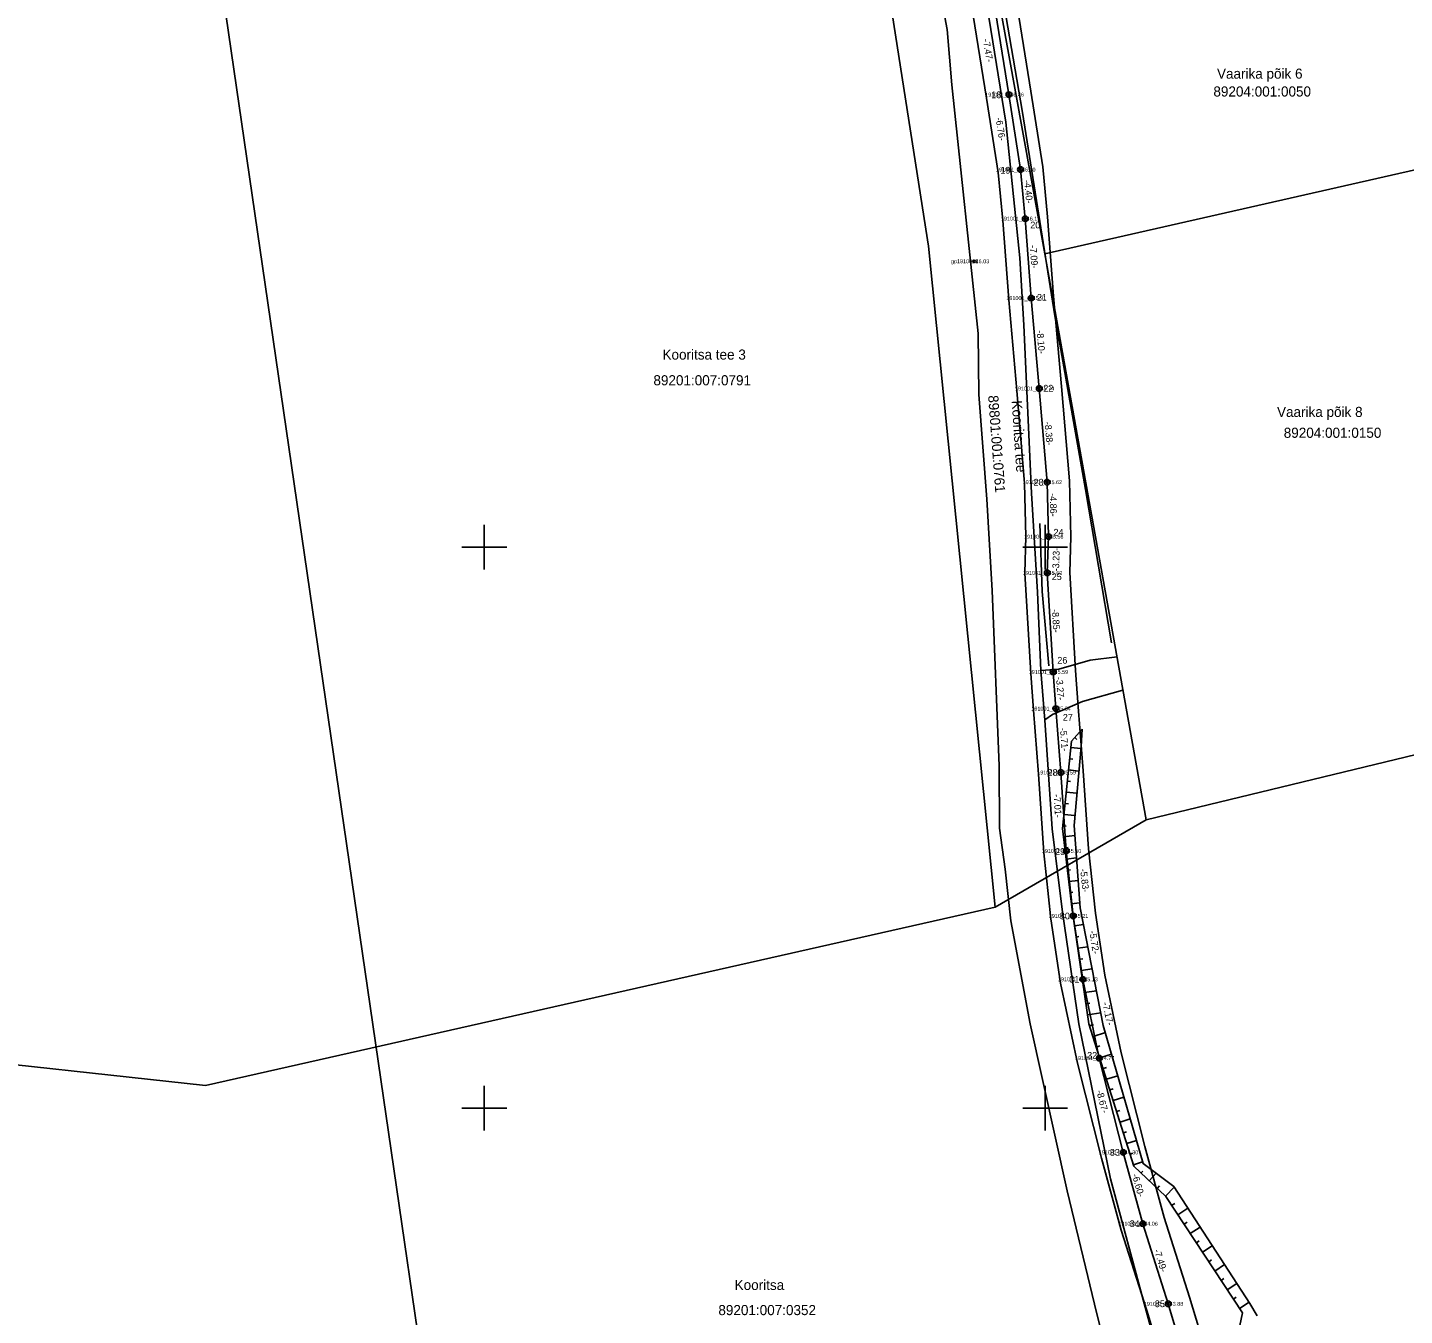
# Model space of a CAD drawing. Extents: x 604066 to 604956, y 6473634 to 6474346.
# Drawn here: x 604559.3 to 604682, y 6473831.5 to 6473946.3 of the extents above; entities that cross this region are included whole.
import ezdxf

# ---------------------------------------------------------------- set-up
doc = ezdxf.new("R2010")
doc.units = 0
for name, color, linetype in [('AED', 7, 'Continuous'), ('JOONSIDE', 7, 'Continuous'), ('KOORDPUNKT', 7, 'Continuous'), ('MOOTKORG', 7, 'Continuous'), ('MOOTMPUNKT', 7, 'Continuous'), ('MOOTNR', 7, 'Continuous'), ('MOOTPIIR', 7, 'Continuous'), ('PIIR', 7, 'Continuous'), ('RELJEEF', 7, 'Continuous'), ('SITRASS', 7, 'Continuous'), ('TEE', 7, 'Continuous'), ('VEEKOGU', 7, 'Continuous'), ('VORK', 7, 'Continuous'), ('VORMISTUS', 7, 'Continuous')]:
    doc.layers.add(name, color=color, linetype=linetype)

msp = doc.modelspace()

# ---------------------------------------------------------------- linework, layer by layer
at = {"layer": 'AED'}
for points in [[(604649.16, 6474001.13), (604643.74, 6473999.92), (604641.11, 6473999.16), (604639.47, 6473996.69), (604638.82, 6473994.42), (604638.66, 6473991.42), (604639.13, 6473988.4), (604641.21, 6473976.45), (604642.8, 6473969.17), (604644.69, 6473957.97), (604647.99, 6473938.75), (604650.86, 6473920.61), (604653.59, 6473905.15), (604655.9, 6473891.46)], [(604649.52, 6473902.1), (604649.73, 6473896.04), (604650.32, 6473889.41)]]:
    msp.add_lwpolyline(points, dxfattribs=at)
at = {"layer": 'KOORDPUNKT'}
for centre, radius in [((604646.76, 6473940.34), 0.25), ((604646.76, 6473940.34), 0.0221), ((604646.76, 6473940.34), 0.025), ((604646.76, 6473940.34), 0.0161), ((604646.76, 6473940.34), 0.0191), ((604646.76, 6473940.34), 0.0102), ((604646.76, 6473940.34), 0.0132), ((604646.76, 6473940.34), 0.00726), ((604646.76, 6473940.34), 0.0043), ((604647.79, 6473933.66), 0.25), ((604647.79, 6473933.66), 0.0191), ((604647.79, 6473933.66), 0.0221), ((604647.79, 6473933.66), 0.025), ((604647.79, 6473933.66), 0.0161), ((604647.79, 6473933.66), 0.0102), ((604647.79, 6473933.66), 0.0132), ((604647.79, 6473933.66), 0.00726), ((604647.79, 6473933.66), 0.0043), ((604648.22, 6473929.28), 0.25), ((604648.22, 6473929.28), 0.025), ((604648.22, 6473929.28), 0.0161), ((604648.22, 6473929.28), 0.0191), ((604648.22, 6473929.28), 0.0221), ((604648.22, 6473929.28), 0.0043), ((604648.22, 6473929.28), 0.00726), ((604648.22, 6473929.28), 0.0102), ((604648.22, 6473929.28), 0.0132), ((604648.74, 6473922.21), 0.25), ((604648.74, 6473922.21), 0.025), ((604648.74, 6473922.21), 0.0161), ((604648.74, 6473922.21), 0.0191), ((604648.74, 6473922.21), 0.0221), ((604648.74, 6473922.21), 0.00726), ((604648.74, 6473922.21), 0.0102), ((604648.74, 6473922.21), 0.0132), ((604648.74, 6473922.21), 0.0043), ((604649.46, 6473914.15), 0.25), ((604649.46, 6473914.15), 0.0221), ((604649.46, 6473914.15), 0.025), ((604649.46, 6473914.15), 0.0102), ((604649.46, 6473914.15), 0.0132), ((604649.46, 6473914.15), 0.0161), ((604649.46, 6473914.15), 0.0191), ((604649.46, 6473914.15), 0.0043), ((604649.46, 6473914.15), 0.00726), ((604650.16, 6473905.79), 0.25), ((604650.16, 6473905.79), 0.0221), ((604650.16, 6473905.79), 0.025), ((604650.16, 6473905.79), 0.0132), ((604650.16, 6473905.79), 0.0161), ((604650.16, 6473905.79), 0.0191), ((604650.16, 6473905.79), 0.0043), ((604650.16, 6473905.79), 0.00726), ((604650.16, 6473905.79), 0.0102), ((604650.28, 6473900.94), 0.25), ((604650.28, 6473900.94), 0.025), ((604650.28, 6473900.94), 0.0191), ((604650.28, 6473900.94), 0.0221), ((604650.28, 6473900.94), 0.0161), ((604650.28, 6473900.94), 0.0102), ((604650.28, 6473900.94), 0.0132), ((604650.28, 6473900.94), 0.00726), ((604650.28, 6473900.94), 0.0043), ((604650.18, 6473897.71), 0.25), ((604650.18, 6473897.71), 0.0221), ((604650.18, 6473897.71), 0.025), ((604650.18, 6473897.71), 0.0191), ((604650.18, 6473897.71), 0.0102), ((604650.18, 6473897.71), 0.0132), ((604650.18, 6473897.71), 0.0161), ((604650.18, 6473897.71), 0.0043), ((604650.18, 6473897.71), 0.00726), ((604650.7, 6473888.87), 0.25), ((604650.7, 6473888.87), 0.0221), ((604650.7, 6473888.87), 0.025), ((604650.7, 6473888.87), 0.0161), ((604650.7, 6473888.87), 0.0191), ((604650.7, 6473888.87), 0.0132), ((604650.7, 6473888.87), 0.00726), ((604650.7, 6473888.87), 0.0102), ((604650.7, 6473888.87), 0.0043), ((604650.94, 6473885.61), 0.25), ((604650.94, 6473885.61), 0.025), ((604650.94, 6473885.61), 0.0191), ((604650.94, 6473885.61), 0.0221), ((604650.94, 6473885.61), 0.0161), ((604650.94, 6473885.61), 0.0102), ((604650.94, 6473885.61), 0.0132), ((604650.94, 6473885.61), 0.00726), ((604650.94, 6473885.61), 0.0043), ((604651.39, 6473879.92), 0.25), ((604651.39, 6473879.92), 0.0191), ((604651.39, 6473879.92), 0.0221), ((604651.39, 6473879.92), 0.025), ((604651.39, 6473879.92), 0.0102), ((604651.39, 6473879.92), 0.0132), ((604651.39, 6473879.92), 0.0161), ((604651.39, 6473879.92), 0.00726), ((604651.39, 6473879.92), 0.0043), ((604651.87, 6473872.93), 0.25), ((604651.87, 6473872.93), 0.0191), ((604651.87, 6473872.93), 0.0221), ((604651.87, 6473872.93), 0.025), ((604651.87, 6473872.93), 0.0102), ((604651.87, 6473872.93), 0.0132), ((604651.87, 6473872.93), 0.0161), ((604651.87, 6473872.93), 0.0043), ((604651.87, 6473872.93), 0.00726), ((604652.49, 6473867.13), 0.25), ((604652.49, 6473867.13), 0.0221), ((604652.49, 6473867.13), 0.025), ((604652.49, 6473867.13), 0.0132), ((604652.49, 6473867.13), 0.0161), ((604652.49, 6473867.13), 0.0191), ((604652.49, 6473867.13), 0.0043), ((604652.49, 6473867.13), 0.00726), ((604652.49, 6473867.13), 0.0102), ((604653.34, 6473861.48), 0.25), ((604653.34, 6473861.48), 0.025), ((604653.34, 6473861.48), 0.0132), ((604653.34, 6473861.48), 0.0161), ((604653.34, 6473861.48), 0.0191), ((604653.34, 6473861.48), 0.0221), ((604653.34, 6473861.48), 0.0043), ((604653.34, 6473861.48), 0.00726), ((604653.34, 6473861.48), 0.0102), ((604654.82, 6473854.46), 0.25), ((604654.82, 6473854.46), 0.0221), ((604654.82, 6473854.46), 0.025), ((604654.82, 6473854.46), 0.0161), ((604654.82, 6473854.46), 0.0191), ((604654.82, 6473854.46), 0.0102), ((604654.82, 6473854.46), 0.0132), ((604654.82, 6473854.46), 0.00726), ((604654.82, 6473854.46), 0.0043), ((604656.95, 6473846.06), 0.25), ((604656.95, 6473846.06), 0.025), ((604656.95, 6473846.06), 0.0161), ((604656.95, 6473846.06), 0.0191), ((604656.95, 6473846.06), 0.0221), ((604656.95, 6473846.06), 0.0132), ((604656.95, 6473846.06), 0.00726), ((604656.95, 6473846.06), 0.0102), ((604656.95, 6473846.06), 0.0043), ((604658.69, 6473839.7), 0.25), ((604658.69, 6473839.7), 0.0191), ((604658.69, 6473839.7), 0.0221), ((604658.69, 6473839.7), 0.025), ((604658.69, 6473839.7), 0.0102), ((604658.69, 6473839.7), 0.0132), ((604658.69, 6473839.7), 0.0161), ((604658.69, 6473839.7), 0.0043), ((604658.69, 6473839.7), 0.00726), ((604660.96, 6473832.56), 0.25), ((604660.96, 6473832.56), 0.025), ((604660.96, 6473832.56), 0.0161), ((604660.96, 6473832.56), 0.0191), ((604660.96, 6473832.56), 0.0221), ((604660.96, 6473832.56), 0.00726), ((604660.96, 6473832.56), 0.0102), ((604660.96, 6473832.56), 0.0132), ((604660.96, 6473832.56), 0.0043)]:
    msp.add_circle(centre, radius, dxfattribs=at)
at = {"layer": 'MOOTMPUNKT'}
for centre in [(604646.76, 6473940.34), (604647.79, 6473933.66), (604648.22, 6473929.28), (604643.66, 6473925.49), (604648.74, 6473922.21), (604649.46, 6473914.15), (604650.16, 6473905.79), (604650.28, 6473900.94), (604650.18, 6473897.71), (604650.7, 6473888.87), (604650.94, 6473885.61), (604651.39, 6473879.92), (604651.87, 6473872.93), (604652.49, 6473867.13), (604653.34, 6473861.48), (604654.82, 6473854.46), (604656.95, 6473846.06), (604658.69, 6473839.7), (604660.96, 6473832.56)]:
    msp.add_circle(centre, 0.1, dxfattribs=at)
at = {"layer": 'MOOTPIIR'}
for points in [[(604665.14, 6473825.6), (604662.87, 6473833.15), (604660.61, 6473840.26), (604658.88, 6473846.57), (604656.77, 6473854.92), (604655.31, 6473861.84), (604654.47, 6473867.39), (604653.87, 6473873.1), (604653.39, 6473880.07), (604652.94, 6473885.76), (604652.7, 6473889.01), (604652.18, 6473897.73), (604652.28, 6473900.93), (604652.15, 6473905.9), (604651.46, 6473914.32), (604650.73, 6473922.37), (604650.21, 6473929.45), (604649.78, 6473933.91), (604648.73, 6473940.65), (604647.53, 6473948.05)], [(604643.58, 6473947.38), (604644.78, 6473940.03), (604645.81, 6473933.41), (604646.23, 6473929.11), (604646.75, 6473922.05), (604647.47, 6473913.97), (604648.16, 6473905.69), (604648.28, 6473900.94), (604648.18, 6473897.68), (604648.71, 6473888.74), (604648.95, 6473885.46), (604649.4, 6473879.77), (604649.88, 6473872.75), (604650.5, 6473866.88), (604651.37, 6473861.13), (604652.87, 6473854.01), (604655.01, 6473845.55), (604656.78, 6473839.13), (604659.05, 6473831.97), (604661.31, 6473824.45)]]:
    msp.add_lwpolyline(points, dxfattribs=at)
at = {"layer": 'PIIR'}
for points in [[(604645.55, 6473867.92), (604639.6, 6473926.84), (604628.65, 6473996.82), (604636.64, 6473998.53), (604636.91, 6473997.15), (604642.13, 6473970.12), (604646.1, 6473947.47), (604649.97, 6473926.14), (604659, 6473875.69)], [(604524, 6473968.82), (604628.65, 6473996.82), (604639.6, 6473926.84), (604645.55, 6473867.92), (604575.16, 6473852.02), (604549.55, 6473854.82)], [(604697.68, 6473959.53), (604702.56, 6473938.89), (604702.74, 6473938.11), (604649.97, 6473926.14), (604646.1, 6473947.47)], [(604702.74, 6473938.11), (604714.62, 6473889.17), (604659, 6473875.69), (604649.97, 6473926.14)]]:
    msp.add_lwpolyline(points, close=True, dxfattribs=at)
msp.add_lwpolyline([(604392.23, 6473874.61), (604414.7, 6473872.41), (604426.55, 6473871.03), (604444.65, 6473869.66), (604482.63, 6473866.81), (604486.98, 6473866.41), (604549.55, 6473854.82), (604575.16, 6473852.02), (604645.55, 6473867.92), (604659, 6473875.69), (604714.62, 6473889.17), (604776, 6473903.81), (604824.84, 6473905.94), (604833.54, 6473909.5), (604821.94, 6473844.68), (604680.66, 6473747.8), (604687.73, 6473704.56), (604422.99, 6473691.29), (604421.99, 6473694.09), (604395.15, 6473723.9)], dxfattribs=at)
at = {"layer": 'RELJEEF'}
for p, q in [((604652.63, 6473883.03), (604652.81, 6473882.87)), ((604652.29, 6473882.14), (604653.17, 6473882.05)), ((604652.09, 6473880.15), (604653, 6473880.05)), ((604652.19, 6473881.14), (604652.46, 6473881.11)), ((604651.99, 6473879.15), (604652.26, 6473879.12)), ((604651.88, 6473878.16), (604652.82, 6473878.06)), ((604651.78, 6473877.16), (604652.07, 6473877.13)), ((604651.58, 6473875.17), (604651.88, 6473875.14)), ((604651.68, 6473876.17), (604652.65, 6473876.07)), ((604651.64, 6473874.18), (604652.63, 6473874.3)), ((604651.76, 6473873.19), (604652.04, 6473873.22)), ((604651.88, 6473872.19), (604652.78, 6473872.3)), ((604651.99, 6473871.2), (604652.25, 6473871.23)), ((604652.11, 6473870.21), (604652.93, 6473870.3)), ((604652.23, 6473869.21), (604652.46, 6473869.24)), ((604652.34, 6473868.22), (604653.07, 6473868.31)), ((604652.47, 6473867.23), (604652.69, 6473867.26)), ((604652.62, 6473866.24), (604653.4, 6473866.36)), ((604652.77, 6473865.25), (604653.01, 6473865.29)), ((604652.91, 6473864.26), (604653.79, 6473864.39)), ((604653.06, 6473863.27), (604653.34, 6473863.31)), ((604653.2, 6473862.28), (604654.18, 6473862.43)), ((604653.35, 6473861.29), (604653.66, 6473861.34)), ((604653.49, 6473860.3), (604654.57, 6473860.46)), ((604653.64, 6473859.31), (604653.98, 6473859.36)), ((604653.79, 6473858.33), (604654.95, 6473858.5)), ((604653.96, 6473857.34), (604654.3, 6473857.45)), ((604654.26, 6473856.39), (604655.36, 6473856.74)), ((604654.56, 6473855.43), (604654.88, 6473855.54)), ((604654.86, 6473854.48), (604655.91, 6473854.81)), ((604655.16, 6473853.53), (604655.47, 6473853.62)), ((604655.46, 6473852.57), (604656.47, 6473852.89)), ((604655.76, 6473851.62), (604656.06, 6473851.71)), ((604656.06, 6473850.67), (604657.02, 6473850.97)), ((604656.36, 6473849.71), (604656.64, 6473849.8)), ((604656.67, 6473848.76), (604657.57, 6473849.05)), ((604656.97, 6473847.81), (604657.23, 6473847.89)), ((604657.27, 6473846.85), (604658.13, 6473847.12)), ((604657.57, 6473845.9), (604657.82, 6473845.98)), ((604657.87, 6473844.94), (604658.68, 6473845.2)), ((604658.54, 6473844.22), (604658.7, 6473844.39)), ((604659.26, 6473843.53), (604659.88, 6473844.19)), ((604659.99, 6473842.84), (604660.2, 6473843.06)), ((604660.71, 6473842.15), (604661.49, 6473842.97)), ((604661.27, 6473841.32), (604661.54, 6473841.5)), ((604661.82, 6473840.49), (604662.71, 6473841.08)), ((604662.37, 6473839.65), (604662.64, 6473839.83)), ((604662.92, 6473838.82), (604663.8, 6473839.4)), ((604663.47, 6473837.98), (604663.73, 6473838.16)), ((604664.02, 6473837.15), (604664.89, 6473837.72)), ((604664.57, 6473836.31), (604664.83, 6473836.49)), ((604665.12, 6473835.48), (604665.99, 6473836.05)), ((604665.67, 6473834.64), (604665.93, 6473834.81)), ((604666.22, 6473833.81), (604667.08, 6473834.37)), ((604666.77, 6473832.97), (604667.02, 6473833.14)), ((604667.32, 6473832.14), (604668.17, 6473832.69))]:
    msp.add_line(p, q, dxfattribs=at)
for points in [[(604653.29, 6473883.78), (604652.35, 6473882.7), (604651.55, 6473874.93), (604652.41, 6473867.67), (604653.9, 6473857.52), (604657.91, 6473844.82), (604660.75, 6473842.12), (604667.57, 6473831.75), (604666.64, 6473827.23), (604667.87, 6473819.03), (604671.63, 6473805.55), (604673.03, 6473793.22), (604675.1, 6473781.3)], [(604653.29, 6473883.78), (604653.19, 6473882.22), (604652.57, 6473875.19), (604653.11, 6473867.86), (604655.17, 6473857.38), (604658.72, 6473845.06), (604661.46, 6473843.01), (604668.23, 6473832.6), (604668.88, 6473831.5)]]:
    msp.add_lwpolyline(points, dxfattribs=at)
at = {"layer": 'SITRASS'}
msp.add_lwpolyline([(604645.56, 6473947.72), (604646.76, 6473940.34), (604647.79, 6473933.66), (604648.22, 6473929.28), (604648.74, 6473922.21), (604649.46, 6473914.15), (604650.16, 6473905.79), (604650.28, 6473900.94), (604650.18, 6473897.71), (604650.7, 6473888.87), (604650.94, 6473885.61), (604651.39, 6473879.92), (604651.87, 6473872.93), (604652.49, 6473867.13), (604653.34, 6473861.48), (604654.82, 6473854.46), (604656.95, 6473846.06), (604658.69, 6473839.7), (604660.96, 6473832.56), (604663.23, 6473825.02)], dxfattribs=at)
at = {"layer": 'TEE'}
for points in [[(604648.52, 6474002.92), (604644.27, 6474001.65), (604640.52, 6474000.14), (604638.25, 6473997.57), (604637.05, 6473994.53), (604636.78, 6473992.15), (604637.27, 6473988), (604640, 6473976.17), (604641.01, 6473969.99), (604643.32, 6473957.55), (604646.5, 6473937.87), (604647.73, 6473925.79), (604648.09, 6473919.8), (604648.79, 6473904.83), (604649.3, 6473896), (604649.61, 6473889), (604649.96, 6473884.59), (604650.62, 6473874.9), (604651.53, 6473867.46), (604652.99, 6473857.52), (604655.83, 6473843.7), (604658.81, 6473832.59), (604663.41, 6473815.74)], [(604624.27, 6473998.3), (604626.35, 6473998.03), (604629.09, 6473996.87), (604631.51, 6473994.38), (604632.49, 6473990.22), (604632.77, 6473987.41), (604635.58, 6473975.26), (604636.85, 6473969.11), (604638.56, 6473961.45), (604639.29, 6473956.57), (604641.25, 6473946.14), (604641.68, 6473941.22), (604644.02, 6473919.05), (604644.07, 6473913.61), (604644.8, 6473904.28), (604645.26, 6473896.15), (604645.91, 6473880.5), (604645.92, 6473874.95), (604646.44, 6473871.29), (604646.95, 6473866.69), (604648.67, 6473857.5), (604651.95, 6473842.63), (604654.6, 6473831.66), (604658.7, 6473815.39)], [(604656.4, 6473890.23), (604654, 6473889.93), (604651.22, 6473889.13), (604649.61, 6473889.02)], [(604649.96, 6473884.61), (604650.64, 6473885.08), (604653.32, 6473886.24), (604656.93, 6473887.27)]]:
    msp.add_lwpolyline(points, dxfattribs=at)
at = {"layer": 'VEEKOGU'}
msp.add_lwpolyline([(604653.29, 6473883.78), (604652.35, 6473882.7), (604651.55, 6473874.93), (604652.41, 6473867.67), (604653.9, 6473857.52), (604657.91, 6473844.82), (604660.75, 6473842.12), (604667.57, 6473831.75)], dxfattribs=at)
at = {"layer": 'VORK'}
for p, q in [((604600, 6473902), (604600, 6473898)), ((604650, 6473902), (604650, 6473898)), ((604598, 6473900), (604602, 6473900)), ((604648, 6473900), (604652, 6473900)), ((604600, 6473852), (604600, 6473848)), ((604650, 6473852), (604650, 6473848)), ((604598, 6473850), (604602, 6473850)), ((604648, 6473850), (604652, 6473850))]:
    msp.add_line(p, q, dxfattribs=at)
at = {"layer": 'VORMISTUS'}
msp.add_lwpolyline([(604563.86, 6474037.6), (604705.86, 6474058.26), (604764.62, 6473654.52), (604622.61, 6473633.85)], close=True, dxfattribs=at)

# ---------------------------------------------------------------- texts
at = {"layer": 'JOONSIDE'}
for s, rotation, p in [('-7.47-', 279.2305, (604644.44, 6473945.26)), ('-6.76-', 278.8325, (604645.57, 6473938.26)), ('-4.40-', 275.5577, (604648.11, 6473932.71)), ('-7.09-', 274.2134, (604648.62, 6473926.92)), ('-8.10-', 275.1374, (604649.23, 6473919.3)), ('-8.38-', 274.7301, (604649.94, 6473911.15)), ('-4.86-', 271.4622, (604650.4, 6473904.81)), ('-3.23-', 88.2804, (604651.23, 6473897.84)), ('-8.85-', 273.357, (604650.6, 6473894.46)), ('-3.27-', 274.2577, (604650.96, 6473888.42)), ('-5.71-', 274.5203, (604651.31, 6473883.88)), ('-7.01-', 273.9196, (604650.74, 6473877.96)), ('-5.83-', 276.0502, (604653.11, 6473871.31)), ('-5.72-', 278.5625, (604653.93, 6473865.78)), ('-7.17-', 281.9335, (604655.08, 6473859.38)), ('-8.67-', 284.1997, (604654.55, 6473851.53)), ('-6.60-', 285.3465, (604657.73, 6473844.06)), ('-7.49-', 287.6123, (604659.68, 6473837.33))]:
    msp.add_text(s, height=0.6, rotation=rotation, dxfattribs=at).set_placement(p)
at = {"layer": 'KOORDPUNKT'}
for s, p in [('18 ', (604645.19, 6473940.02)), ('19 ', (604646.01, 6473933.3)), ('20 ', (604648.67, 6473928.42)), ('21 ', (604649.26, 6473921.97)), ('22 ', (604649.83, 6473913.87)), ('23 ', (604648.96, 6473905.49)), ('24 ', (604650.74, 6473901.03)), ('25 ', (604650.58, 6473897.07)), ('26 ', (604651.08, 6473889.62)), ('27 ', (604651.57, 6473884.53)), ('28 ', (604650.21, 6473879.62)), ('29 ', (604650.88, 6473872.57)), ('30 ', (604651.3, 6473866.83)), ('31 ', (604652.15, 6473861.18)), ('32 ', (604653.74, 6473854.41)), ('33 ', (604655.76, 6473845.76)), ('34 ', (604657.52, 6473839.4)), ('35 ', (604659.77, 6473832.26))]:
    msp.add_text(s, height=0.6, dxfattribs=at).set_placement(p)
at = {"layer": 'MOOTKORG'}
for s, p in [(' 46.46', (604646.76, 6473940.16)), (' 46.20', (604647.79, 6473933.48)), (' 46.11', (604648.22, 6473929.11)), (' 46.03', (604643.66, 6473925.31)), (' 45.91', (604648.74, 6473922.03)), (' 45.74', (604649.46, 6473913.97)), (' 45.62', (604650.16, 6473905.62)), (' 45.56', (604650.28, 6473900.76)), (' 45.60', (604650.18, 6473897.53)), (' 45.59', (604650.7, 6473888.7)), (' 45.54', (604650.94, 6473885.44)), (' 45.59', (604651.39, 6473879.74)), (' 45.50', (604651.87, 6473872.75)), (' 45.21', (604652.49, 6473866.96)), (' 45.13', (604653.34, 6473861.31)), (' 44.77', (604654.82, 6473854.29)), (' 44.30', (604656.95, 6473845.88)), (' 44.06', (604658.69, 6473839.52)), (' 43.88', (604660.96, 6473832.38))]:
    msp.add_text(s, height=0.35, dxfattribs=at).set_placement(p)
at = {"layer": 'MOOTNR'}
for s, p in [('191001_21 ', (604644.66, 6473940.16)), ('191001_22 ', (604645.62, 6473933.48)), ('191001_23 ', (604646.05, 6473929.11)), ('gp1910011 ', (604641.6, 6473925.31)), ('191001_24 ', (604646.54, 6473922.03)), ('191001_25 ', (604647.3, 6473913.97)), ('191001_26 ', (604647.99, 6473905.62)), ('191001_27 ', (604648.11, 6473900.76)), ('191001_28 ', (604648.01, 6473897.53)), ('191001_29 ', (604648.53, 6473888.7)), ('191001_30 ', (604648.77, 6473885.44)), ('191001_31 ', (604649.29, 6473879.74)), ('191001_32 ', (604649.7, 6473872.75)), ('191001_33 ', (604650.32, 6473866.96)), ('191001_34 ', (604651.13, 6473861.31)), ('191001_35 ', (604652.65, 6473854.29)), ('191001_37 ', (604654.78, 6473845.88)), ('191001_38 ', (604656.52, 6473839.52)), ('191001_39 ', (604658.79, 6473832.38))]:
    msp.add_text(s, height=0.35, dxfattribs=at).set_placement(p)
at = {"layer": 'PIIR'}
for s, p in [('Vaarika põik 6', (604665.31, 6473941.76)), ('89204:001:0050', (604664.99, 6473940.17)), ('Kooritsa tee 3', (604615.89, 6473916.72)), ('89201:007:0791', (604615.08, 6473914.43)), ('Vaarika põik 8', (604670.66, 6473911.61)), ('89204:001:0150', (604671.26, 6473909.75)), ('Kooritsa', (604622.32, 6473833.79)), ('89201:007:0352', (604620.87, 6473831.55))]:
    msp.add_text(s, height=0.9, dxfattribs=at).set_placement(p)
for s, rotation, p in [('89801:001:0761', 274.2466, (604644.91, 6473913.51)), ('Kooritsa tee', 273.7222, (604647.01, 6473913.05))]:
    msp.add_text(s, height=0.9, rotation=rotation, dxfattribs=at).set_placement(p)

doc.saveas('drawing.dxf')
